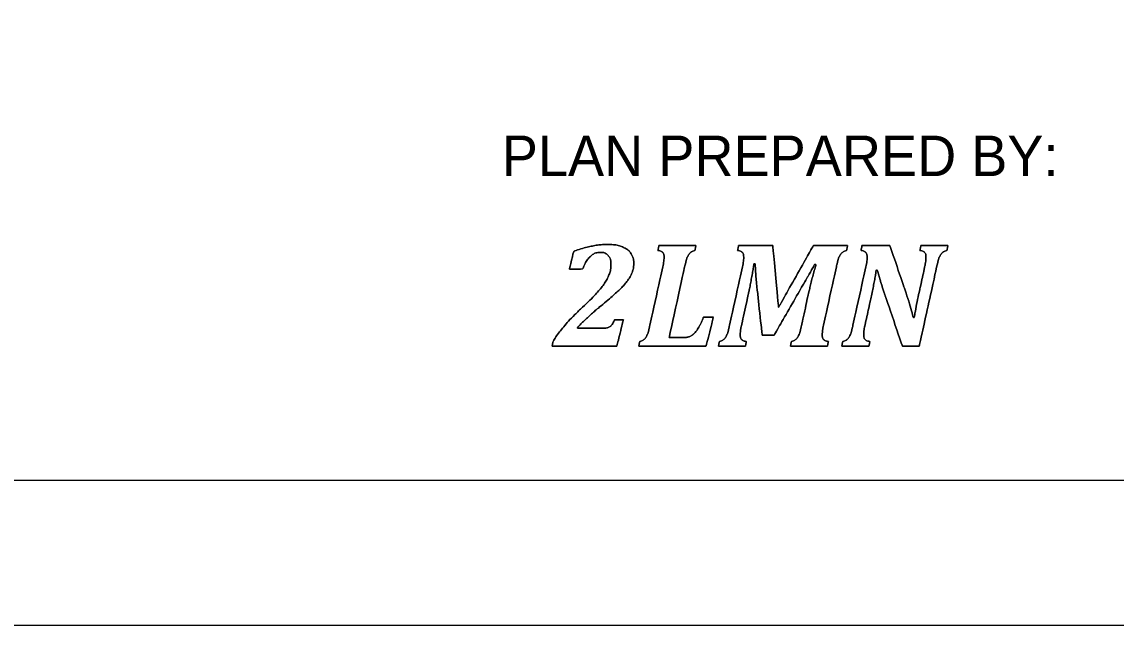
# Model space of a CAD drawing. Extents: x 0 to 34, y 0 to 22.
# Drawn here: x 1.954 to 5.736, y 0 to 2.086 of the extents above; entities that cross this region are included whole.
import ezdxf

# ---------------------------------------------------------------- set-up
doc = ezdxf.new("R2010")
doc.units = 0
for name, color, linetype in [('SH_Border', 7, 'Continuous'), ('SH_Cut_Line', 7, 'Continuous'), ('SH_Data', 7, 'Continuous'), ('SH_Text', 7, 'Continuous')]:
    doc.layers.add(name, color=color, linetype=linetype)

msp = doc.modelspace()

# ---------------------------------------------------------------- linework, layer by layer
at = {"layer": 'SH_Border'}
msp.add_lwpolyline([(1.5, 21.5), (33.5, 21.5), (33.5, 0.5), (1.5, 0.5)], close=True, dxfattribs=at)
at = {"layer": 'SH_Cut_Line'}
msp.add_lwpolyline([(0, 0), (34, 0), (34, 22), (0, 22)], close=True, dxfattribs=at)
at = {"layer": 'SH_Data'}
for points in [[(3.9579, 1.0268), (3.9667, 1.0268), (3.9735, 1.0274), (3.9784, 1.0287), (3.9832, 1.03), (3.9873, 1.0323), (3.9907, 1.0358), (3.9941, 1.0393), (3.9978, 1.0459), (4.0019, 1.0556), (4.0019, 1.0556), (4.0329, 1.0556), (4.0329, 1.0556), (4.0329, 1.0556), (4.0102, 0.9643), (4.0102, 0.9643), (4.0102, 0.9643), (3.7864, 0.9643), (3.7864, 0.9643), (3.7864, 0.9643), (3.79, 0.9811), (3.79, 0.9811), (3.7989, 0.9966), (3.8112, 1.0136), (3.8268, 1.0321), (3.8424, 1.0507), (3.8642, 1.0733), (3.8923, 1.1), (3.9181, 1.1243), (3.9374, 1.1442), (3.9504, 1.1596), (3.9634, 1.175), (3.9732, 1.1898), (3.9799, 1.2041), (3.9866, 1.2184), (3.9899, 1.2332), (3.9899, 1.2485), (3.9899, 1.2609), (3.9867, 1.2707), (3.9803, 1.2779), (3.9738, 1.2852), (3.9652, 1.2888), (3.9543, 1.2888), (3.9406, 1.2888), (3.9288, 1.2841), (3.9188, 1.2747), (3.9088, 1.2654), (3.9001, 1.251), (3.8929, 1.2316), (3.8929, 1.2316), (3.8466, 1.2316), (3.8466, 1.2316), (3.8466, 1.2316), (3.8611, 1.2929), (3.8611, 1.2929), (3.8867, 1.3017), (3.9082, 1.3078), (3.9258, 1.3112), (3.9433, 1.3146), (3.9609, 1.3163), (3.9785, 1.3163), (3.9988, 1.3163), (4.0158, 1.3135), (4.0294, 1.3078), (4.0431, 1.3021), (4.053, 1.2944), (4.0593, 1.2847), (4.0655, 1.275), (4.0687, 1.264), (4.0687, 1.2518), (4.0687, 1.2404), (4.0668, 1.2296), (4.0631, 1.2195), (4.0594, 1.2094), (4.0532, 1.1989), (4.0447, 1.1879), (4.0361, 1.1769), (4.0245, 1.1647), (4.0099, 1.1511), (3.9952, 1.1376), (3.9748, 1.1201), (3.9485, 1.0985), (3.9361, 1.0883), (3.9228, 1.0765), (3.9085, 1.0633), (3.8942, 1.05), (3.8828, 1.0387), (3.8743, 1.0293), (3.8743, 1.0293), (3.8738, 1.0268), (3.8738, 1.0268), (3.8738, 1.0268), (3.9579, 1.0268), (3.9579, 1.0268)], [(3.9579, 1.0268), (3.9579, 1.0268), (3.8738, 1.0268), (3.8738, 1.0268), (3.8738, 1.0268), (3.8743, 1.0293), (3.8743, 1.0293), (3.8828, 1.0387), (3.8942, 1.05), (3.9085, 1.0633), (3.9228, 1.0765), (3.9361, 1.0883), (3.9485, 1.0985), (3.9748, 1.1201), (3.9952, 1.1376), (4.0099, 1.1511), (4.0245, 1.1647), (4.0361, 1.1769), (4.0447, 1.1879), (4.0532, 1.1989), (4.0594, 1.2094), (4.0631, 1.2195), (4.0668, 1.2296), (4.0687, 1.2404), (4.0687, 1.2518), (4.0687, 1.264), (4.0655, 1.275), (4.0593, 1.2847), (4.053, 1.2944), (4.0431, 1.3021), (4.0294, 1.3078), (4.0158, 1.3135), (3.9988, 1.3163), (3.9785, 1.3163), (3.9609, 1.3163), (3.9433, 1.3146), (3.9258, 1.3112), (3.9082, 1.3078), (3.8867, 1.3017), (3.8611, 1.2929), (3.8611, 1.2929), (3.8466, 1.2316), (3.8466, 1.2316), (3.8466, 1.2316), (3.8929, 1.2316), (3.8929, 1.2316), (3.9001, 1.251), (3.9088, 1.2654), (3.9188, 1.2747), (3.9288, 1.2841), (3.9406, 1.2888), (3.9543, 1.2888), (3.9652, 1.2888), (3.9738, 1.2852), (3.9803, 1.2779), (3.9867, 1.2707), (3.9899, 1.2609), (3.9899, 1.2485), (3.9899, 1.2332), (3.9866, 1.2184), (3.9799, 1.2041), (3.9732, 1.1898), (3.9634, 1.175), (3.9504, 1.1596), (3.9374, 1.1442), (3.9181, 1.1243), (3.8923, 1.1), (3.8642, 1.0733), (3.8424, 1.0507), (3.8268, 1.0321), (3.8112, 1.0136), (3.7989, 0.9966), (3.79, 0.9811), (3.79, 0.9811), (3.7864, 0.9643), (3.7864, 0.9643), (3.7864, 0.9643), (4.0102, 0.9643), (4.0102, 0.9643), (4.0102, 0.9643), (4.0329, 1.0556), (4.0329, 1.0556), (4.0329, 1.0556), (4.0019, 1.0556), (4.0019, 1.0556), (3.9978, 1.0459), (3.9941, 1.0393), (3.9907, 1.0358), (3.9873, 1.0323), (3.9832, 1.03), (3.9784, 1.0287), (3.9735, 1.0274), (3.9667, 1.0268), (3.9579, 1.0268)], [(4.2389, 0.9946), (4.2472, 0.9946), (4.2536, 0.9953), (4.2582, 0.9967), (4.2628, 0.998), (4.2669, 1.0001), (4.2707, 1.003), (4.2744, 1.0059), (4.2785, 1.0099), (4.283, 1.015), (4.2875, 1.0201), (4.2919, 1.0268), (4.2963, 1.0349), (4.3007, 1.0431), (4.3052, 1.0533), (4.3098, 1.0655), (4.3098, 1.0655), (4.3443, 1.0655), (4.3443, 1.0655), (4.3443, 1.0655), (4.3184, 0.9643), (4.3184, 0.9643), (4.3184, 0.9643), (4.086, 0.9643), (4.086, 0.9643), (4.086, 0.9643), (4.0895, 0.9811), (4.0895, 0.9811), (4.0966, 0.9831), (4.1021, 0.9859), (4.1059, 0.9895), (4.1097, 0.9931), (4.113, 0.9982), (4.1157, 1.0047), (4.1184, 1.0112), (4.1211, 1.0207), (4.1238, 1.0331), (4.1238, 1.0331), (4.1701, 1.2436), (4.1701, 1.2436), (4.1723, 1.2537), (4.1734, 1.2636), (4.1734, 1.2735), (4.1734, 1.2806), (4.1717, 1.2858), (4.1684, 1.2892), (4.1651, 1.2925), (4.1597, 1.2946), (4.1523, 1.2957), (4.1523, 1.2957), (4.1558, 1.3125), (4.1558, 1.3125), (4.1558, 1.3125), (4.2836, 1.3125), (4.2836, 1.3125), (4.2836, 1.3125), (4.2801, 1.2957), (4.2801, 1.2957), (4.273, 1.2936), (4.2675, 1.2908), (4.2637, 1.2873), (4.2599, 1.2837), (4.2566, 1.2786), (4.2539, 1.2721), (4.2512, 1.2655), (4.2485, 1.256), (4.2458, 1.2436), (4.2458, 1.2436), (4.1909, 0.9946), (4.1909, 0.9946), (4.1909, 0.9946), (4.2389, 0.9946), (4.2389, 0.9946)], [(4.2389, 0.9946), (4.2389, 0.9946), (4.1909, 0.9946), (4.1909, 0.9946), (4.1909, 0.9946), (4.2458, 1.2436), (4.2458, 1.2436), (4.2485, 1.256), (4.2512, 1.2655), (4.2539, 1.2721), (4.2566, 1.2786), (4.2599, 1.2837), (4.2637, 1.2873), (4.2675, 1.2908), (4.273, 1.2936), (4.2801, 1.2957), (4.2801, 1.2957), (4.2836, 1.3125), (4.2836, 1.3125), (4.2836, 1.3125), (4.1558, 1.3125), (4.1558, 1.3125), (4.1558, 1.3125), (4.1523, 1.2957), (4.1523, 1.2957), (4.1597, 1.2946), (4.1651, 1.2925), (4.1684, 1.2892), (4.1717, 1.2858), (4.1734, 1.2806), (4.1734, 1.2735), (4.1734, 1.2636), (4.1723, 1.2537), (4.1701, 1.2436), (4.1701, 1.2436), (4.1238, 1.0331), (4.1238, 1.0331), (4.1211, 1.0207), (4.1184, 1.0112), (4.1157, 1.0047), (4.113, 0.9982), (4.1097, 0.9931), (4.1059, 0.9895), (4.1021, 0.9859), (4.0966, 0.9831), (4.0895, 0.9811), (4.0895, 0.9811), (4.086, 0.9643), (4.086, 0.9643), (4.086, 0.9643), (4.3184, 0.9643), (4.3184, 0.9643), (4.3184, 0.9643), (4.3443, 1.0655), (4.3443, 1.0655), (4.3443, 1.0655), (4.3098, 1.0655), (4.3098, 1.0655), (4.3052, 1.0533), (4.3007, 1.0431), (4.2963, 1.0349), (4.2919, 1.0268), (4.2875, 1.0201), (4.283, 1.015), (4.2785, 1.0099), (4.2744, 1.0059), (4.2707, 1.003), (4.2669, 1.0001), (4.2628, 0.998), (4.2582, 0.9967), (4.2536, 0.9953), (4.2472, 0.9946), (4.2389, 0.9946)], [(4.5496, 1.3125), (4.5496, 1.3125), (4.5695, 1.0995), (4.5695, 1.0995), (4.5695, 1.0995), (4.6899, 1.3125), (4.6899, 1.3125), (4.6899, 1.3125), (4.808, 1.3125), (4.808, 1.3125), (4.808, 1.3125), (4.8045, 1.2957), (4.8045, 1.2957), (4.7974, 1.2936), (4.7919, 1.2908), (4.7881, 1.2873), (4.7843, 1.2837), (4.781, 1.2786), (4.7783, 1.2721), (4.7756, 1.2655), (4.7729, 1.256), (4.7702, 1.2436), (4.7702, 1.2436), (4.7239, 1.0331), (4.7239, 1.0331), (4.7229, 1.0287), (4.7222, 1.0252), (4.7219, 1.0227), (4.7216, 1.0201), (4.7213, 1.0174), (4.721, 1.0144), (4.7208, 1.0114), (4.7206, 1.0077), (4.7206, 1.0033), (4.7206, 0.9962), (4.7223, 0.9909), (4.7256, 0.9876), (4.7289, 0.9843), (4.7343, 0.9821), (4.7417, 0.9811), (4.7417, 0.9811), (4.7382, 0.9643), (4.7382, 0.9643), (4.7382, 0.9643), (4.6104, 0.9643), (4.6104, 0.9643), (4.6104, 0.9643), (4.6139, 0.9811), (4.6139, 0.9811), (4.621, 0.9831), (4.6265, 0.9859), (4.6303, 0.9895), (4.6341, 0.9931), (4.6374, 0.9982), (4.6401, 1.0047), (4.6428, 1.0112), (4.6455, 1.0207), (4.6482, 1.0331), (4.6482, 1.0331), (4.6716, 1.1403), (4.6716, 1.1403), (4.6741, 1.1519), (4.6778, 1.1673), (4.6825, 1.1866), (4.6873, 1.2059), (4.6928, 1.2261), (4.699, 1.2472), (4.699, 1.2472), (4.694, 1.2472), (4.694, 1.2472), (4.686, 1.2326), (4.6774, 1.2173), (4.6683, 1.2015), (4.6683, 1.2015), (4.554, 1.0028), (4.554, 1.0028), (4.554, 1.0028), (4.5128, 1.0028), (4.5128, 1.0028), (4.5128, 1.0028), (4.496, 1.1561), (4.496, 1.1561), (4.4938, 1.1755), (4.4922, 1.1924), (4.4911, 1.2069), (4.49, 1.2213), (4.4891, 1.2356), (4.4884, 1.2497), (4.4884, 1.2497), (4.4843, 1.2497), (4.4843, 1.2497), (4.482, 1.2341), (4.4789, 1.2162), (4.4752, 1.196), (4.4715, 1.1759), (4.4681, 1.1589), (4.465, 1.1451), (4.465, 1.1451), (4.4404, 1.0331), (4.4404, 1.0331), (4.4394, 1.0287), (4.4387, 1.0252), (4.4384, 1.0227), (4.438, 1.0201), (4.4377, 1.0174), (4.4375, 1.0144), (4.4372, 1.0114), (4.4371, 1.0077), (4.4371, 1.0033), (4.4371, 0.9962), (4.4387, 0.9909), (4.442, 0.9876), (4.4453, 0.9843), (4.4507, 0.9821), (4.4582, 0.9811), (4.4582, 0.9811), (4.4546, 0.9643), (4.4546, 0.9643), (4.4546, 0.9643), (4.3614, 0.9643), (4.3614, 0.9643), (4.3614, 0.9643), (4.3649, 0.9811), (4.3649, 0.9811), (4.372, 0.9831), (4.3775, 0.9859), (4.3813, 0.9895), (4.3851, 0.9931), (4.3884, 0.9982), (4.3911, 1.0047), (4.3938, 1.0112), (4.3965, 1.0207), (4.3992, 1.0331), (4.3992, 1.0331), (4.4455, 1.2436), (4.4455, 1.2436), (4.4477, 1.2537), (4.4488, 1.2636), (4.4488, 1.2735), (4.4488, 1.2806), (4.4471, 1.2858), (4.4438, 1.2892), (4.4405, 1.2925), (4.4351, 1.2946), (4.4277, 1.2957), (4.4277, 1.2957), (4.4312, 1.3125), (4.4312, 1.3125), (4.4312, 1.3125), (4.5496, 1.3125), (4.5496, 1.3125)], [(4.5496, 1.3125), (4.5496, 1.3125), (4.4312, 1.3125), (4.4312, 1.3125), (4.4312, 1.3125), (4.4277, 1.2957), (4.4277, 1.2957), (4.4351, 1.2946), (4.4405, 1.2925), (4.4438, 1.2892), (4.4471, 1.2858), (4.4488, 1.2806), (4.4488, 1.2735), (4.4488, 1.2636), (4.4477, 1.2537), (4.4455, 1.2436), (4.4455, 1.2436), (4.3992, 1.0331), (4.3992, 1.0331), (4.3965, 1.0207), (4.3938, 1.0112), (4.3911, 1.0047), (4.3884, 0.9982), (4.3851, 0.9931), (4.3813, 0.9895), (4.3775, 0.9859), (4.372, 0.9831), (4.3649, 0.9811), (4.3649, 0.9811), (4.3614, 0.9643), (4.3614, 0.9643), (4.3614, 0.9643), (4.4546, 0.9643), (4.4546, 0.9643), (4.4546, 0.9643), (4.4582, 0.9811), (4.4582, 0.9811), (4.4507, 0.9821), (4.4453, 0.9843), (4.442, 0.9876), (4.4387, 0.9909), (4.4371, 0.9962), (4.4371, 1.0033), (4.4371, 1.0077), (4.4372, 1.0114), (4.4375, 1.0144), (4.4377, 1.0174), (4.438, 1.0201), (4.4384, 1.0227), (4.4387, 1.0252), (4.4394, 1.0287), (4.4404, 1.0331), (4.4404, 1.0331), (4.465, 1.1451), (4.465, 1.1451), (4.4681, 1.1589), (4.4715, 1.1759), (4.4752, 1.196), (4.4789, 1.2162), (4.482, 1.2341), (4.4843, 1.2497), (4.4843, 1.2497), (4.4884, 1.2497), (4.4884, 1.2497), (4.4891, 1.2356), (4.49, 1.2213), (4.4911, 1.2069), (4.4922, 1.1924), (4.4938, 1.1755), (4.496, 1.1561), (4.496, 1.1561), (4.5128, 1.0028), (4.5128, 1.0028), (4.5128, 1.0028), (4.554, 1.0028), (4.554, 1.0028), (4.554, 1.0028), (4.6683, 1.2015), (4.6683, 1.2015), (4.6774, 1.2173), (4.686, 1.2326), (4.694, 1.2472), (4.694, 1.2472), (4.699, 1.2472), (4.699, 1.2472), (4.6928, 1.2261), (4.6873, 1.2059), (4.6825, 1.1866), (4.6778, 1.1673), (4.6741, 1.1519), (4.6716, 1.1403), (4.6716, 1.1403), (4.6482, 1.0331), (4.6482, 1.0331), (4.6455, 1.0207), (4.6428, 1.0112), (4.6401, 1.0047), (4.6374, 0.9982), (4.6341, 0.9931), (4.6303, 0.9895), (4.6265, 0.9859), (4.621, 0.9831), (4.6139, 0.9811), (4.6139, 0.9811), (4.6104, 0.9643), (4.6104, 0.9643), (4.6104, 0.9643), (4.7382, 0.9643), (4.7382, 0.9643), (4.7382, 0.9643), (4.7417, 0.9811), (4.7417, 0.9811), (4.7343, 0.9821), (4.7289, 0.9843), (4.7256, 0.9876), (4.7223, 0.9909), (4.7206, 0.9962), (4.7206, 1.0033), (4.7206, 1.0077), (4.7208, 1.0114), (4.721, 1.0144), (4.7213, 1.0174), (4.7216, 1.0201), (4.7219, 1.0227), (4.7222, 1.0252), (4.7229, 1.0287), (4.7239, 1.0331), (4.7239, 1.0331), (4.7702, 1.2436), (4.7702, 1.2436), (4.7729, 1.256), (4.7756, 1.2655), (4.7783, 1.2721), (4.781, 1.2786), (4.7843, 1.2837), (4.7881, 1.2873), (4.7919, 1.2908), (4.7974, 1.2936), (4.8045, 1.2957), (4.8045, 1.2957), (4.808, 1.3125), (4.808, 1.3125), (4.808, 1.3125), (4.6899, 1.3125), (4.6899, 1.3125), (4.6899, 1.3125), (4.5695, 1.0995), (4.5695, 1.0995), (4.5695, 1.0995), (4.5496, 1.3125), (4.5496, 1.3125)], [(4.8578, 1.3125), (4.8578, 1.3125), (4.9544, 1.3125), (4.9544, 1.3125), (4.9544, 1.3125), (5.0034, 1.1681), (5.0034, 1.1681), (5.0168, 1.1288), (5.0274, 1.0941), (5.0352, 1.064), (5.0352, 1.064), (5.0385, 1.064), (5.0385, 1.064), (5.0434, 1.0934), (5.0498, 1.126), (5.0578, 1.1617), (5.0578, 1.1617), (5.0756, 1.2436), (5.0756, 1.2436), (5.0778, 1.2538), (5.0789, 1.2638), (5.0789, 1.2735), (5.0789, 1.2806), (5.0772, 1.2858), (5.0739, 1.2892), (5.0706, 1.2925), (5.0653, 1.2946), (5.0578, 1.2957), (5.0578, 1.2957), (5.0614, 1.3125), (5.0614, 1.3125), (5.0614, 1.3125), (5.1549, 1.3125), (5.1549, 1.3125), (5.1549, 1.3125), (5.1513, 1.2957), (5.1513, 1.2957), (5.1442, 1.2936), (5.1387, 1.2908), (5.1349, 1.2873), (5.1311, 1.2837), (5.1278, 1.2786), (5.1251, 1.2721), (5.1224, 1.2655), (5.1197, 1.256), (5.117, 1.2436), (5.117, 1.2436), (5.0558, 0.9643), (5.0558, 0.9643), (5.0558, 0.9643), (4.9978, 0.9643), (4.9978, 0.9643), (4.9978, 0.9643), (4.9369, 1.1426), (4.9369, 1.1426), (4.9321, 1.1565), (4.9279, 1.1696), (4.9242, 1.1818), (4.9204, 1.1939), (4.9159, 1.2093), (4.9107, 1.2281), (4.9107, 1.2281), (4.9069, 1.2283), (4.9069, 1.2283), (4.9055, 1.2169), (4.9029, 1.2012), (4.8991, 1.1812), (4.8953, 1.1613), (4.8908, 1.1396), (4.8855, 1.1163), (4.8855, 1.1163), (4.8672, 1.0331), (4.8672, 1.0331), (4.8662, 1.0287), (4.8655, 1.0252), (4.8652, 1.0227), (4.8649, 1.0201), (4.8646, 1.0174), (4.8643, 1.0144), (4.8641, 1.0114), (4.8639, 1.0077), (4.8639, 1.0033), (4.8639, 0.9962), (4.8656, 0.9909), (4.8689, 0.9876), (4.8722, 0.9843), (4.8776, 0.9821), (4.885, 0.9811), (4.885, 0.9811), (4.8815, 0.9643), (4.8815, 0.9643), (4.8815, 0.9643), (4.788, 0.9643), (4.788, 0.9643), (4.788, 0.9643), (4.7915, 0.9811), (4.7915, 0.9811), (4.7986, 0.9831), (4.8041, 0.9859), (4.8079, 0.9895), (4.8117, 0.9931), (4.815, 0.9982), (4.8177, 1.0047), (4.8204, 1.0112), (4.8231, 1.0207), (4.8258, 1.0331), (4.8258, 1.0331), (4.8721, 1.2436), (4.8721, 1.2436), (4.8743, 1.2537), (4.8754, 1.2636), (4.8754, 1.2735), (4.8754, 1.2806), (4.8737, 1.2858), (4.8704, 1.2892), (4.8671, 1.2925), (4.8617, 1.2946), (4.8543, 1.2957), (4.8543, 1.2957), (4.8578, 1.3125), (4.8578, 1.3125)], [(4.8578, 1.3125), (4.8578, 1.3125), (4.8543, 1.2957), (4.8543, 1.2957), (4.8617, 1.2946), (4.8671, 1.2925), (4.8704, 1.2892), (4.8737, 1.2858), (4.8754, 1.2806), (4.8754, 1.2735), (4.8754, 1.2636), (4.8743, 1.2537), (4.8721, 1.2436), (4.8721, 1.2436), (4.8258, 1.0331), (4.8258, 1.0331), (4.8231, 1.0207), (4.8204, 1.0112), (4.8177, 1.0047), (4.815, 0.9982), (4.8117, 0.9931), (4.8079, 0.9895), (4.8041, 0.9859), (4.7986, 0.9831), (4.7915, 0.9811), (4.7915, 0.9811), (4.788, 0.9643), (4.788, 0.9643), (4.788, 0.9643), (4.8815, 0.9643), (4.8815, 0.9643), (4.8815, 0.9643), (4.885, 0.9811), (4.885, 0.9811), (4.8776, 0.9821), (4.8722, 0.9843), (4.8689, 0.9876), (4.8656, 0.9909), (4.8639, 0.9962), (4.8639, 1.0033), (4.8639, 1.0077), (4.8641, 1.0114), (4.8643, 1.0144), (4.8646, 1.0174), (4.8649, 1.0201), (4.8652, 1.0227), (4.8655, 1.0252), (4.8662, 1.0287), (4.8672, 1.0331), (4.8672, 1.0331), (4.8855, 1.1163), (4.8855, 1.1163), (4.8908, 1.1396), (4.8953, 1.1613), (4.8991, 1.1812), (4.9029, 1.2012), (4.9055, 1.2169), (4.9069, 1.2283), (4.9069, 1.2283), (4.9107, 1.2281), (4.9107, 1.2281), (4.9159, 1.2093), (4.9204, 1.1939), (4.9242, 1.1818), (4.9279, 1.1696), (4.9321, 1.1565), (4.9369, 1.1426), (4.9369, 1.1426), (4.9978, 0.9643), (4.9978, 0.9643), (4.9978, 0.9643), (5.0558, 0.9643), (5.0558, 0.9643), (5.0558, 0.9643), (5.117, 1.2436), (5.117, 1.2436), (5.1197, 1.256), (5.1224, 1.2655), (5.1251, 1.2721), (5.1278, 1.2786), (5.1311, 1.2837), (5.1349, 1.2873), (5.1387, 1.2908), (5.1442, 1.2936), (5.1513, 1.2957), (5.1513, 1.2957), (5.1549, 1.3125), (5.1549, 1.3125), (5.1549, 1.3125), (5.0614, 1.3125), (5.0614, 1.3125), (5.0614, 1.3125), (5.0578, 1.2957), (5.0578, 1.2957), (5.0653, 1.2946), (5.0706, 1.2925), (5.0739, 1.2892), (5.0772, 1.2858), (5.0789, 1.2806), (5.0789, 1.2735), (5.0789, 1.2638), (5.0778, 1.2538), (5.0756, 1.2436), (5.0756, 1.2436), (5.0578, 1.1617), (5.0578, 1.1617), (5.0498, 1.126), (5.0434, 1.0934), (5.0385, 1.064), (5.0385, 1.064), (5.0352, 1.064), (5.0352, 1.064), (5.0274, 1.0941), (5.0168, 1.1288), (5.0034, 1.1681), (5.0034, 1.1681), (4.9544, 1.3125), (4.9544, 1.3125), (4.9544, 1.3125), (4.8578, 1.3125), (4.8578, 1.3125)]]:
    msp.add_open_spline(points, degree=3, dxfattribs=at)

# ---------------------------------------------------------------- texts
at = {"layer": 'SH_Text'}
msp.add_text('PLAN PREPARED BY:', height=0.14, dxfattribs=at).set_placement((3.6125, 1.553))

doc.saveas('drawing.dxf')
